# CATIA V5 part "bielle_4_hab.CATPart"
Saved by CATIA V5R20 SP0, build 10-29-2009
Part number: bielle_4_hab
Bounding box of the stored display mesh (mm): x 0.15 to 0.2, y 1.42 to 1.62, z 1.3 to 2.5
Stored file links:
  D:\Dropbox\IAO_2012\IAO_2012_718_ccascaro\ccascaro\bielle_4_hab.CATPart
  C:\Users\Cédric\Documents\IFMA-2A\IAO\Projet IAO\Projet IAO catia\ass_bielles_skl.CATProduct
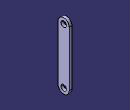
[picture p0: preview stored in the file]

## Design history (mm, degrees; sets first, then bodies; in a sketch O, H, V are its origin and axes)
Set1
  Point1 "point E": linked copy from another document
  Point2 "point F": linked copy from another document
Body1 (main body)
  Sketch1 on yz-plane, origin (0, 0, 0), H (0, 1, 0), V (0, 0, 1)
    construction line L1 (1.52, 2.4) -> (1.52, 1.4)
    point P1 (1.52, 2.4)
    point P2 (1.52, 1.4)
    line L2 (1.62, 2.4) -> (1.62, 1.4)
    line L3 (1.42, 1.4) -> (1.42, 2.4)
    arc A1 centre (1.52, 1.4) radius 0.1 from (1.62, 1.4) to (1.42, 1.4) cw
    arc A2 centre (1.52, 2.4) radius 0.1 from (1.42, 2.4) to (1.62, 2.4) cw
    reference projected point E1 (1.52, 2.4) from Point1
    reference projected point E2 (1.52, 1.4) from Point2
    circle A3 centre (1.52, 2.4) radius 0.05
    circle A4 centre (1.52, 1.4) radius 0.05
    distance L1 L2 = 0.1
    distance P1 E1 = 0
    distance P2 E2 = 0
    tangency: A1 L2, A2 L2, A1 L3, A2 L3
  Pad1: profile Sketch1, direction (1, 0, 0), length 0.2, opposite side length -0.15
